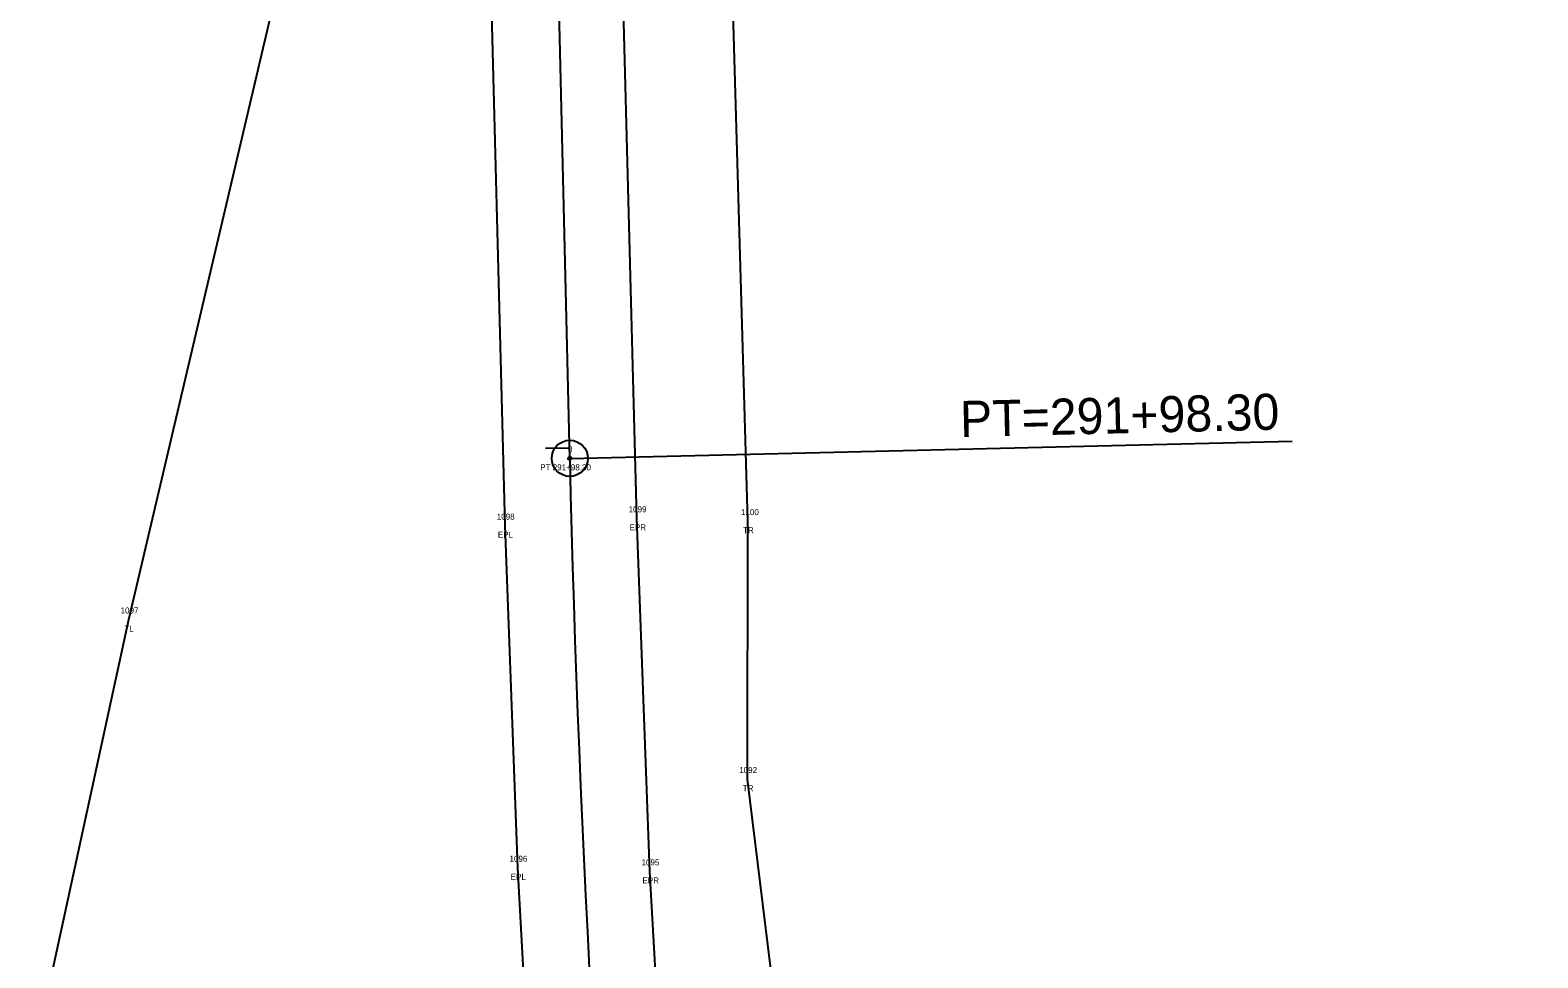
# Model space of a CAD drawing. Extents: x 2445178 to 2446205, y 790762 to 792372.
# Drawn here: x 2445599.8 to 2445850.4, y 792018.7 to 792172.9 of the extents above; entities that cross this region are included whole.
import ezdxf

# ---------------------------------------------------------------- set-up
doc = ezdxf.new("R2010")
doc.units = 0
for name, color, linetype in [('RD_EX_Road', 7, 'Continuous'), ('RD_EX_Road_txCode', 7, 'Continuous'), ('RD_EX_VEG', 7, 'Continuous'), ('RD_EX_VEG_txCode', 7, 'Continuous'), ('RD_HC_Cl', 7, 'Continuous'), ('RD_HC_Data', 7, 'Continuous'), ('RD_HC_Data_Tic', 7, 'Continuous'), ('RD_HC_txCode', 7, 'Continuous'), ('RD_SMD_Locator', 7, 'Continuous')]:
    doc.layers.add(name, color=color, linetype=linetype)

msp = doc.modelspace()

# ---------------------------------------------------------------- linework, layer by layer
at = {"layer": 'RD_EX_Road'}
for points in [[(2445780.98, 791497.5), (2445766.72, 791558.1), (2445751.9, 791628.3), (2445743.63, 791673.52), (2445732.07, 791741.61), (2445728.16, 791765.65), (2445723.56, 791768), (2445722.11, 791770.23), (2445723.91, 791773.52), (2445727.13, 791775.28), (2445723.51, 791799.48), (2445721.07, 791816.02), (2445719.51, 791817.06), (2445719.65, 791821.33), (2445720.29, 791823.76), (2445714.87, 791872.94), (2445710.18, 791923.37), (2445705.3, 791989.12), (2445702.81, 792033.07), (2445700.66, 792091.77), (2445697.78, 792201.78), (2445695.41, 792302.8)], [(2445850.42, 791174.36), (2445823.13, 791264.7), (2445806.34, 791321.46), (2445789.41, 791379.89), (2445773.46, 791437.57), (2445759.36, 791494.22), (2445744.01, 791559.83), (2445740.09, 791577.64), (2445731.05, 791621.01), (2445722.21, 791669.43), (2445711, 791738.26), (2445706.49, 791765.2), (2445707.32, 791765.82), (2445706.36, 791771.19), (2445705.53, 791771.38), (2445701.96, 791795.92), (2445699.57, 791813.34), (2445693.24, 791870.48), (2445688.14, 791921.92), (2445683.42, 791987.19), (2445680.88, 792033.67), (2445678.74, 792090.55), (2445675.91, 792199.23), (2445673.61, 792301.11)]]:
    msp.add_lwpolyline(points, dxfattribs=at)
at = {"layer": 'RD_EX_VEG'}
for points in [[(2445687.12, 791815.07), (2445675.71, 791865.82), (2445647.64, 791894.24), (2445625.38, 791951.76), (2445599.8, 791999.43), (2445616.22, 792074.95), (2445645.15, 792198.05), (2445661.49, 792301.38)], [(2445729.92, 791827.7), (2445734.27, 791924.48), (2445719.05, 792048.41), (2445719.1, 792091.3), (2445713.04, 792300.82)]]:
    msp.add_lwpolyline(points, dxfattribs=at)
at = {"layer": 'RD_HC_Cl'}
msp.add_line((2445689.49, 792101.74), (2445684.79, 792300.91), dxfattribs=at)
msp.add_arc((2448553.48, 792169.37), 2864.79, 181.3527, 196.84356, dxfattribs=at)
at = {"layer": 'RD_HC_Data'}
msp.add_line((2445689.49, 792101.74), (2445809.58, 792104.57), dxfattribs=at)
for radius in [3, 0.282]:
    msp.add_circle((2445689.49, 792101.74), radius, dxfattribs=at)
at = {"layer": 'RD_HC_Data_Tic'}
msp.add_line((2445689.45, 792103.44), (2445685.45, 792103.35), dxfattribs=at)
at = {"layer": 'RD_SMD_Locator'}
for centre in [(2445689.49, 792101.74), (2445700.66, 792091.77), (2445719.1, 792091.3), (2445678.74, 792090.55), (2445616.22, 792074.95), (2445719.05, 792048.41), (2445680.88, 792033.67), (2445702.81, 792033.07)]:
    msp.add_circle(centre, 0.001, dxfattribs=at)

# ---------------------------------------------------------------- texts
at = {"layer": 'RD_EX_Road_txCode'}
for s, p in [('1099', (2445699.28, 792092.77)), ('1098', (2445677.36, 792091.55)), ('EPL', (2445677.54, 792088.55)), ('EPR', (2445699.43, 792089.77)), ('1096', (2445679.47, 792034.67)), ('1095', (2445701.42, 792034.07)), ('EPL', (2445679.68, 792031.67)), ('EPR', (2445701.58, 792031.07))]:
    msp.add_text(s, height=1, dxfattribs=at).set_placement(p)
at = {"layer": 'RD_EX_VEG_txCode'}
for s, p in [('1100', (2445717.96, 792092.3)), ('TR', (2445718.3, 792089.3)), ('1097', (2445614.83, 792075.95)), ('TL', (2445615.45, 792072.95)), ('1092', (2445717.66, 792049.41)), ('TR', (2445718.25, 792046.41))]:
    msp.add_text(s, height=1, dxfattribs=at).set_placement(p)
at = {"layer": 'RD_HC_Data'}
msp.add_text('PT=291+98.30', height=6, rotation=1.3527, dxfattribs=at).set_placement((2445754.43, 792105.27))
at = {"layer": 'RD_HC_txCode'}
for s, p in [('8', (2445689.21, 792102.74)), ('PT 291+98.30', (2445684.58, 792099.74))]:
    msp.add_text(s, height=1, dxfattribs=at).set_placement(p)

doc.saveas('drawing.dxf')
